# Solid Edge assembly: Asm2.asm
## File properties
Author: Sarvanan
Template: sync ansi assembly.asm
Last saved by: TIET
Revision: 17
Application: Solid Edge
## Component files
end plate.par
disk.par
support pin.par
spacer.par
center pin.par
bolt.par
nut.par
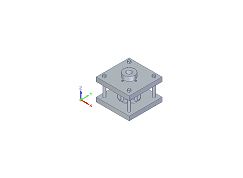
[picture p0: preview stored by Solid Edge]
